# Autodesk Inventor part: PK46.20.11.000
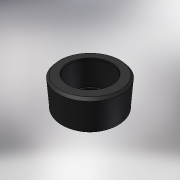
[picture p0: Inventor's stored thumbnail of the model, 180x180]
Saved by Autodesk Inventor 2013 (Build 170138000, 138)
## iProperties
Created: 2012-02
Part Number: PK46.20.11.000
Material: Silicone
Document SubType Name: Modeling
Designer: tedescj
Mass: 18.6674 g
Surface Area: 71.6929 cm^2
Volume: 14.934 cm^3
Density: 1.25 g/cm^3
Author: tedescj
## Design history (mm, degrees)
derived "PK46.20.10.000.ipt"
feature "Stitch Surface1"
combine "Combine2"
  body "Solid3"
feature "PK46.20.11.000::PK46.20.10.000.ipt" dims "d0" = 10
tag "TaggingFeature1"
body "Solid1"
feature "Composite1"
body "Srf1"
